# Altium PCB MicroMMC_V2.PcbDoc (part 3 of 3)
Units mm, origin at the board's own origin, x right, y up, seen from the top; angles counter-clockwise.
Board outline 100.01 x 100 mm, 4 copper layers (TOP01, GND02, POWER03, BOTTOM04); 302 components, 195 nets, 1017 pads, 817 vias.
Unrouted connection lines stored in the file: 7.
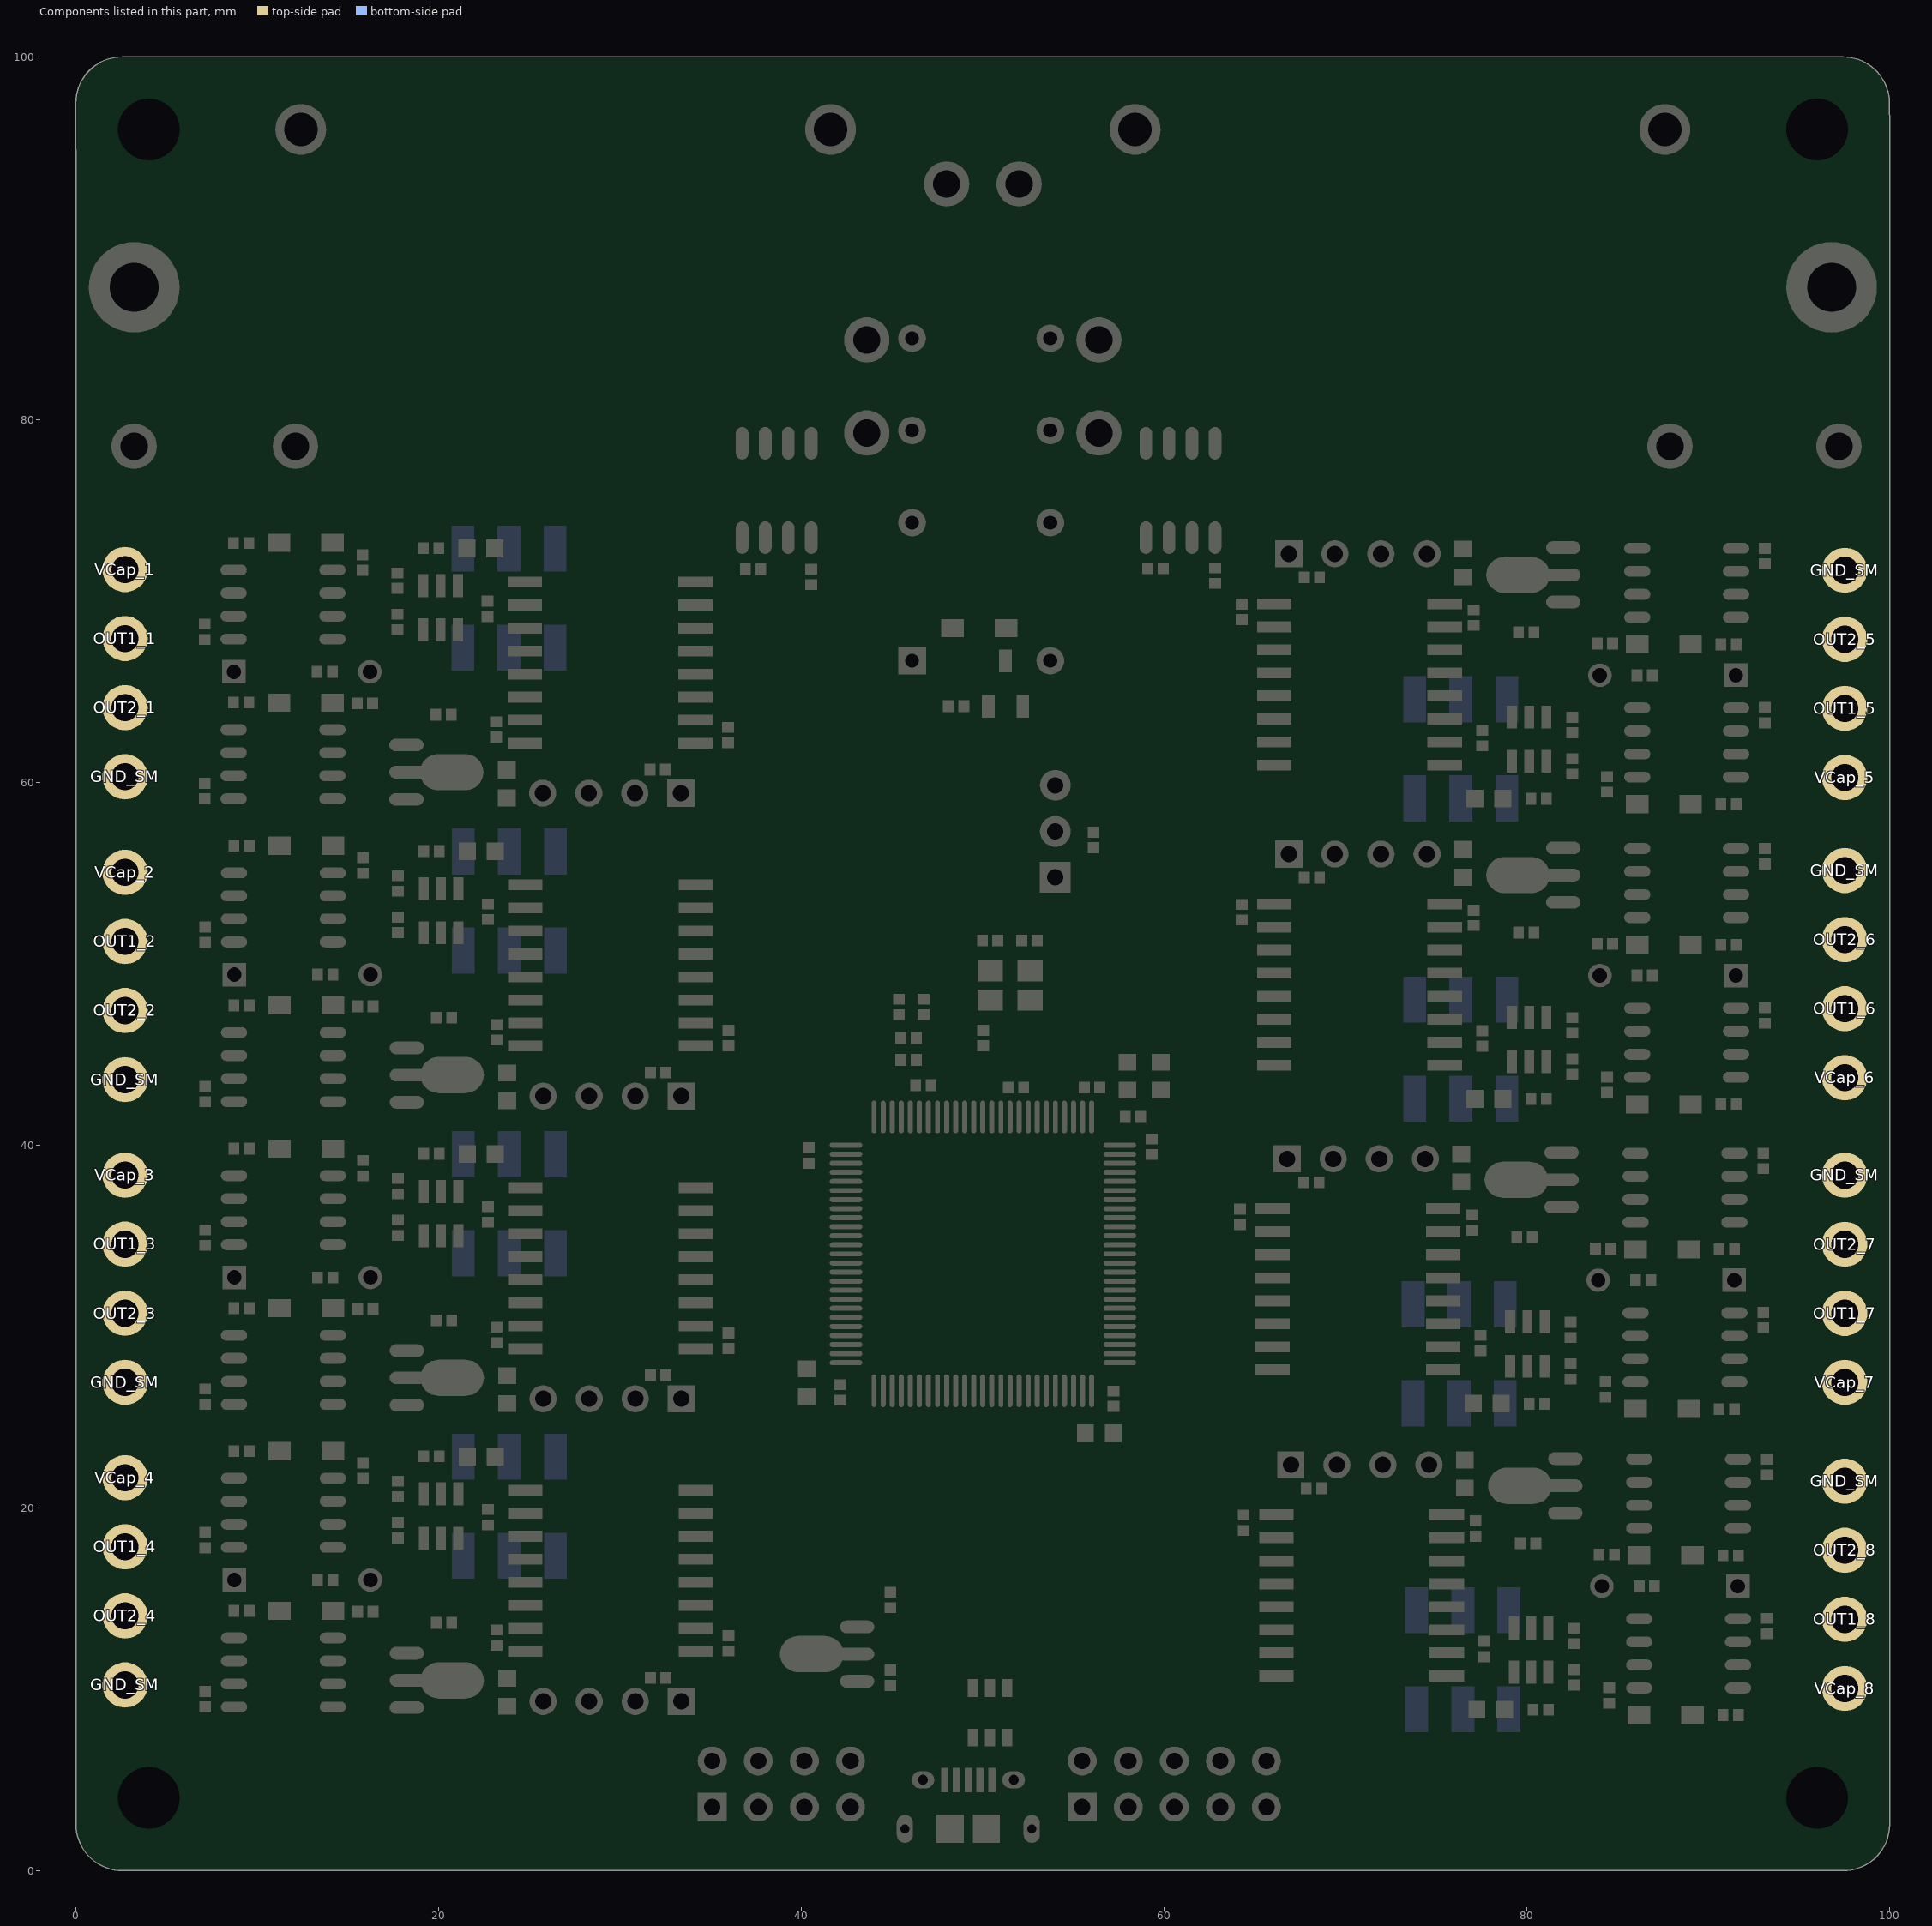
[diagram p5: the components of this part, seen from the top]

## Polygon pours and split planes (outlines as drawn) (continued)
+5 on TOP01 "NONET_L04_P-001" (solid, pour order 937): 63.702,19.245 70.502,19.245 70.502,21.402 70.502,23.674 68.2,23.674 68.2,20.671 63.702,20.671
+5 on TOP01 "NONET_L04_P-001" (solid, pour order 939): 36.6,61.2 32.1,61.2 32.1,58 29.7,58 29.7,62.48 36.6,62.48
GND on TOP01 "NONET_L04_P-001" (solid, remove dead copper, pour order 949): 32.1,74.7 42.5,74.7 42.5,72.5 57.5,72.5 57.5,74.6 57.4,74.7 68.1,74.7 68.1,0.5 68,0.6 32.1,0.6
+5 on TOP01 "TOP01-+5 1" (solid, pour order 928): 39.085,10.785 46.6,10.785 46.6,12.919 37.2,12.919 37.2,12.4 35.648,12.4 32.2,12.4 30.7,12.4 29.7,12.4 29.7,10.1 29.7,7.926 32.1,7.926 32.1,11.369 33.9,11.369 33.9,10.785
GND on TOP01 "TOP01-GND" (solid, pour order 919): 39.1,5 41.4,5 41.4,8.2 46.6,8.2 46.6,10.5 43.949,10.5 43.664,10.785 42.319,10.785 42.114,10.58 42.114,10.435 39.1,10.435 39.1,8.2
VCap_5 on TOP01 "TOP01-VCap_5" (solid, pour order 915): 90.411,64.7 90.411,63.805 94.323,63.805 94.323,66.807 90.698,66.807 86.627,66.807 86.627,64.7
VCap_6 on TOP01 "TOP01-VCap_6" (solid, pour order 914): 90.411,48.144 90.411,47.249 94.323,47.249 94.323,50.251 90.698,50.251 86.627,50.251 86.627,48.144
VCap_7 on TOP01 "TOP01-VCap_7" (solid, pour order 913): 90.32,31.344 90.32,30.449 94.232,30.449 94.232,33.451 90.607,33.451 86.536,33.451 86.536,31.344
VCap_8 on TOP01 "TOP01-VCap_8" (solid, pour order 912): 90.521,14.47 90.521,13.575 94.433,13.575 94.433,16.577 90.808,16.577 86.738,16.577 86.738,14.47
VCap_4 on TOP01 "TOP01-VCap_4" (solid, pour order 911): 9.549,15.12 13.619,15.12 13.619,17.227 9.836,17.227 9.836,18.122 5.924,18.122 5.924,15.12
VCap_3 on TOP01 "TOP01-VCap_3" (solid, pour order 910): 9.549,31.805 13.619,31.805 13.619,33.912 9.836,33.912 9.836,34.807 5.924,34.807 5.924,31.805
VCap_2 on TOP01 "TOP01-VCap_2" (solid, pour order 909): 9.549,48.5 13.619,48.5 13.619,50.607 9.836,50.607 9.836,51.502 5.924,51.502 5.924,48.5
VCap_1 on TOP01 "TOP01-VCap_1" (solid, pour order 908): 9.525,65.2 13.595,65.2 13.595,67.307 9.812,67.307 9.812,68.202 5.9,68.202 5.9,65.2
GND on TOP01 "NONET_L04_P-001" (solid, pour order 903): 57.1,44.1 60.8,44.1 60.8,45.933 57.1,45.933
GND on TOP01 "NONET_L04_P-001" (solid, pour order 902): 47.5,47.494 47.5,44.535 46.59,43.625 46.64,43.575 46.64,40.79 46.36,40.79 46.36,42.39 45.99,42.76 45.99,47.494
3.3V_MC on TOP01 "NONET_L04_P-001" (solid, pour order 901): 44.64,47.744 44.64,49.1 47.44,49.1 47.44,47.744
GND on TOP01 "NONET_L04_P-001" (solid, pour order 899): 55.64,25.891 58.048,25.891 58.048,23.31 56.14,23.31 56.14,24.59 55.36,24.59 55.36,26.083 55.62,26.083 55.64,26.103
+5V_SM on TOP01 "NONET_L04_P-001" (solid, pour order 892): 74.333,11.484 76.687,11.484 76.687,12.634 72.998,12.634 72.998,7.617 74.333,7.617
GND_SM on TOP01 "NONET_L04_P-001" (solid, pour order 884): 77.968,7.777 77.968,10.157 76.67,10.157 76.67,11.027 74.633,11.027 74.633,7.777
GND_SM on TOP01 "NONET_L04_P-001" (solid, pour order 876): 85.303,9.527 85.303,7.777 82.033,7.777 82.033,10.525 83.206,10.525 83.206,9.525
+12_SM on TOP01 "NONET_L04_P-001" (solid, pour order 868): 88.238,7.792 88.238,10.777 83.579,10.777 83.579,9.777 85.471,9.777 85.471,7.788
GND_SM on TOP01 "NONET_L04_P-001" (solid, pour order 860): 94.433,12.178 89.3,12.178 89.3,13.4 94.433,13.4
GND_SM on TOP01 "NONET_L04_P-001" (solid, pour order 852): 99.4,19.778 99.4,23.777 95.533,23.777 95.533,22.127 89.3,22.127 89.3,20.95 95.46,20.95 96.599,19.811
VCap_8 on TOP01 "NONET_L04_P-001" (solid, pour order 844): 95.233,22.252 95.233,23.801 89.3,23.801 89.3,22.252
OUT1_8 on TOP01 "NONET_L04_P-001" (solid, pour order 836): 99.4,11.577 99.4,15.677 94.64,15.677 94.64,11.97 90.521,11.97 90.521,9.147 91.233,9.147 91.233,7.777 95.9,7.777 95.9,11.577
OUT2_8 on TOP01 "NONET_L04_P-001" (solid, pour order 828): 99.4,15.877 94.633,15.877 94.633,16.877 91.358,16.877 91.358,18.177 90.521,18.177 90.521,20.777 95.166,20.777 96.366,19.577 99.4,19.577
+12_SM on TOP01 "NONET_L04_P-001" (solid, pour order 812): 88.175,16.6 84.408,16.6 84.408,18.235 85.538,19.365 88.148,19.365
+5V_SM on TOP01 "NONET_L04_P-001" (solid, pour order 796): 83.683,20.139 83.683,19.695 81.237,17.25 80.191,17.25 80.191,18.79 80.003,18.978 74.098,18.973 74.098,20.219
GND_SM on TOP01 "NONET_L04_P-001" (solid, pour order 788): 83.983,22.171 83.983,20.215 74.098,20.215 74.098,18.73 80.066,18.73 80.066,17.25 71.348,17.25 71.348,23.777 73.267,23.777 73.267,21.342 77.498,21.342 78.566,22.171
+12_SM on TOP01 "NONET_L04_P-001" (solid, pour order 780): 73.267,23.751 73.267,21.447 78.5,21.447 79.225,22.173 79.268,22.13 83.924,22.13 83.924,23.789
+5V_SM on TOP01 "NONET_L04_P-001" (solid, pour order 891): 74.132,28.358 76.485,28.358 76.485,29.508 72.797,29.508 72.797,24.49 74.132,24.491
GND_SM on TOP01 "NONET_L04_P-001" (solid, pour order 883): 77.767,24.651 77.767,27.03 76.468,27.03 76.468,27.901 74.432,27.901 74.432,24.651
GND_SM on TOP01 "NONET_L04_P-001" (solid, pour order 875): 85.102,26.401 85.102,24.651 81.832,24.651 81.832,27.399 83.005,27.399 83.005,26.399
+12_SM on TOP01 "NONET_L04_P-001" (solid, pour order 867): 88.037,24.666 88.037,27.651 83.378,27.651 83.378,26.651 85.27,26.651 85.27,24.662
GND_SM on TOP01 "NONET_L04_P-001" (solid, pour order 859): 94.232,29.052 89.3,29.052 89.3,30.3 94.232,30.3
GND_SM on TOP01 "NONET_L04_P-001" (solid, pour order 851): 99.332,36.651 99.332,40.651 95.332,40.651 95.332,39.001 89.3,39.001 89.3,37.824 95.259,37.824 96.398,36.685
VCap_7 on TOP01 "NONET_L04_P-001" (solid, pour order 843): 95.032,39.126 95.032,40.675 89.3,40.675 89.3,39.126
OUT1_7 on TOP01 "NONET_L04_P-001" (solid, pour order 835): 99.332,28.451 99.332,32.551 94.438,32.551 94.438,28.844 90.32,28.844 90.32,26.021 91.032,26.021 91.032,24.651 95.832,24.651 95.832,28.451
OUT2_7 on TOP01 "NONET_L04_P-001" (solid, pour order 827): 99.332,32.751 94.432,32.751 94.432,33.751 91.157,33.751 91.157,35.051 90.32,35.051 90.32,37.651 94.965,37.651 96.165,36.451 99.332,36.451
+12_SM on TOP01 "NONET_L04_P-001" (solid, pour order 811): 87.974,33.474 84.207,33.474 84.207,35.109 85.337,36.239 87.947,36.239
+5V_SM on TOP01 "NONET_L04_P-001" (solid, pour order 795): 83.482,37.013 83.482,36.569 81.036,34.124 79.99,34.124 79.99,35.664 79.802,35.852 73.896,35.847 73.897,37.093
GND_SM on TOP01 "NONET_L04_P-001" (solid, pour order 787): 83.782,39.045 83.782,37.089 73.897,37.089 73.897,35.604 79.864,35.604 79.864,34.124 71.147,34.124 71.147,40.651 73.066,40.651 73.066,38.216 77.297,38.216 78.364,39.045
+12_SM on TOP01 "NONET_L04_P-001" (solid, pour order 779): 73.066,40.625 73.066,38.321 78.298,38.321 79.023,39.047 79.066,39.004 83.723,39.004 83.723,40.663
+5V_SM on TOP01 "NONET_L04_P-001" (solid, pour order 890): 74.223,45.158 76.576,45.158 76.576,46.308 72.888,46.308 72.888,41.291 74.223,41.291
GND_SM on TOP01 "NONET_L04_P-001" (solid, pour order 882): 77.858,41.451 77.858,43.831 76.559,43.831 76.559,44.701 74.523,44.701 74.523,41.451
GND_SM on TOP01 "NONET_L04_P-001" (solid, pour order 874): 85.193,43.201 85.193,41.451 81.923,41.451 81.923,44.199 83.096,44.199 83.096,43.199
+12_SM on TOP01 "NONET_L04_P-001" (solid, pour order 866): 88.128,41.466 88.128,44.451 83.469,44.451 83.469,43.451 85.361,43.451 85.361,41.462
GND_SM on TOP01 "NONET_L04_P-001" (solid, pour order 858): 94.323,45.852 89.3,45.852 89.3,47.026 94.323,47.026
GND_SM on TOP01 "NONET_L04_P-001" (solid, pour order 850): 99.423,53.451 99.423,57.451 95.423,57.451 95.423,55.801 89.3,55.801 89.3,54.624 95.35,54.624 96.489,53.485
VCap_6 on TOP01 "NONET_L04_P-001" (solid, pour order 842): 95.123,55.926 95.123,57.475 89.3,57.475 89.3,55.926
OUT1_6 on TOP01 "NONET_L04_P-001" (solid, pour order 834): 99.423,45.251 99.423,49.351 94.529,49.351 94.529,45.644 90.411,45.644 90.411,42.821 91.123,42.821 91.123,41.451 95.923,41.451 95.923,45.251
OUT2_6 on TOP01 "NONET_L04_P-001" (solid, pour order 826): 99.423,49.551 94.523,49.551 94.523,50.551 91.248,50.551 91.248,51.851 90.411,51.851 90.411,54.451 95.056,54.451 96.256,53.251 99.423,53.251
+12_SM on TOP01 "NONET_L04_P-001" (solid, pour order 810): 88.065,50.274 84.298,50.274 84.298,51.909 85.428,53.039 88.038,53.039
+5V_SM on TOP01 "NONET_L04_P-001" (solid, pour order 794): 83.573,53.813 83.573,53.369 81.127,50.924 80.08,50.924 80.08,52.464 79.893,52.652 73.987,52.647 73.987,53.893
GND_SM on TOP01 "NONET_L04_P-001" (solid, pour order 786): 83.873,55.845 83.873,53.889 73.987,53.889 73.987,52.404 79.955,52.404 79.955,50.924 71.238,50.924 71.238,57.451 73.157,57.451 73.157,55.016 77.388,55.016 78.455,55.845
+12_SM on TOP01 "NONET_L04_P-001" (solid, pour order 778): 73.157,57.425 73.157,55.121 78.389,55.121 79.114,55.847 79.157,55.804 83.814,55.804 83.814,57.463
+12_SM on TOP01 "NONET_L04_P-001" (solid, pour order 777): 73.157,73.981 73.157,71.677 78.389,71.677 79.114,72.403 79.157,72.36 83.814,72.36 83.814,74.019
GND_SM on TOP01 "NONET_L04_P-001" (solid, remove dead copper, pour order 785): 83.873,72.401 83.873,70.445 73.987,70.445 73.987,68.96 79.955,68.96 79.955,67.48 71.238,67.48 71.238,74.007 73.157,74.007 73.157,71.572 77.388,71.572 78.455,72.401
+5V_SM on TOP01 "NONET_L04_P-001" (solid, pour order 793): 83.573,70.369 83.573,69.925 81.127,67.48 80.08,67.48 80.08,69.02 79.893,69.208 73.987,69.203 73.987,70.449
+12_SM on TOP01 "NONET_L04_P-001" (solid, pour order 809): 88.065,66.83 84.298,66.83 84.298,68.465 85.428,69.595 88.038,69.595
OUT2_5 on TOP01 "NONET_L04_P-001" (solid, pour order 825): 99.423,66.107 94.523,66.107 94.523,67.107 91.248,67.107 91.248,68.407 90.411,68.407 90.411,71.007 95.056,71.007 96.256,69.807 99.423,69.807
OUT1_5 on TOP01 "NONET_L04_P-001" (solid, pour order 833): 99.423,61.807 99.423,65.907 94.529,65.907 94.529,62.2 90.411,62.2 90.411,59.377 91.123,59.377 91.123,58.007 95.923,58.007 95.923,61.807
VCap_5 on TOP01 "NONET_L04_P-001" (solid, pour order 841): 95.123,72.482 95.123,74.031 89.3,74.031 89.3,72.482
GND_SM on TOP01 "NONET_L04_P-001" (solid, pour order 849): 99.423,70.007 99.423,74.007 95.423,74.007 95.423,72.357 89.3,72.357 89.3,71.18 95.35,71.18 96.489,70.041
GND_SM on TOP01 "NONET_L04_P-001" (solid, pour order 857): 94.323,62.408 89.3,62.408 89.3,63.6 94.323,63.6
+12_SM on TOP01 "NONET_L04_P-001" (solid, pour order 865): 88.128,58.022 88.128,61.007 83.469,61.007 83.469,60.007 85.361,60.007 85.361,58.018
GND_SM on TOP01 "NONET_L04_P-001" (solid, pour order 873): 85.193,59.757 85.193,58.007 81.923,58.007 81.923,60.755 83.096,60.755 83.096,59.755
GND_SM on TOP01 "NONET_L04_P-001" (solid, pour order 881): 77.858,58.007 77.858,60.387 76.559,60.387 76.559,61.257 74.523,61.257 74.523,58.007
+5V_SM on TOP01 "NONET_L04_P-001" (solid, pour order 889): 74.223,61.714 76.576,61.714 76.576,62.864 72.888,62.864 72.888,57.847 74.223,57.847
+12_SM on TOP01 "NONET_L04_P-001" (solid, pour order 776): 27.09,7.946 27.09,10.249 21.857,10.249 21.132,9.524 21.089,9.567 16.432,9.567 16.432,7.908
+5V_SM on TOP01 "NONET_L04_P-001" (solid, pour order 792): 16.674,11.558 16.674,12.001 19.119,14.447 20.166,14.447 20.166,12.907 20.354,12.719 26.259,12.723 26.259,11.478
GND_SM on TOP01 "NONET_L04_P-001" (solid, pour order 784): 16.374,9.525 16.374,11.482 26.259,11.482 26.259,12.967 20.291,12.967 20.291,14.447 29,14.447 29,7.92 27.09,7.92 27.09,10.355 22.859,10.355 21.791,9.525
+12_SM on TOP01 "NONET_L04_P-001" (solid, pour order 808): 12.181,15.097 15.949,15.097 15.949,13.462 14.818,12.332 12.209,12.332
OUT2_4 on TOP01 "NONET_L04_P-001" (solid, pour order 824): 0.824,15.82 5.724,15.82 5.724,14.82 8.999,14.82 8.999,13.52 9.836,13.52 9.836,10.92 5.191,10.92 3.991,12.12 0.824,12.12
VCap_4 on TOP01 "NONET_L04_P-001" (solid, pour order 840): 5.124,9.445 5.124,7.896 10.9,7.896 10.9,9.445
GND_SM on TOP01 "NONET_L04_P-001" (solid, pour order 848): 0.824,11.92 0.824,7.92 4.824,7.92 4.824,9.57 10.9,9.57 10.9,10.747 4.897,10.747 3.758,11.886
OUT1_4 on TOP01 "NONET_L04_P-001" (solid, pour order 832): 0.824,20.12 0.824,16.02 5.717,16.02 5.717,19.727 9.836,19.727 9.836,22.55 9.124,22.55 9.124,23.92 4.324,23.92 4.324,20.12
GND_SM on TOP01 "NONET_L04_P-001" (solid, pour order 856): 5.924,19.519 10.9,19.519 10.9,18.3 5.924,18.3
+12_SM on TOP01 "NONET_L04_P-001" (solid, pour order 864): 12.119,23.905 12.119,20.92 16.778,20.92 16.778,21.92 14.886,21.92 14.886,23.908
GND_SM on TOP01 "NONET_L04_P-001" (solid, pour order 872): 15.054,22.169 15.054,23.92 18.324,23.92 18.324,21.172 17.151,21.172 17.151,22.172
GND_SM on TOP01 "NONET_L04_P-001" (solid, pour order 880): 22.388,23.92 22.388,21.54 23.687,21.54 23.687,20.67 25.723,20.67 25.723,23.92
+5V_SM on TOP01 "NONET_L04_P-001" (solid, pour order 888): 26.024,20.213 23.67,20.213 23.67,19.063 27.358,19.063 27.358,24.08 26.024,24.08
+12_SM on TOP01 "NONET_L04_P-001" (solid, pour order 775): 27.09,24.631 27.09,26.934 21.857,26.934 21.132,26.209 21.089,26.252 16.432,26.252 16.432,24.593
+5V_SM on TOP01 "NONET_L04_P-001" (solid, pour order 791): 16.674,28.243 16.674,28.686 19.119,31.132 20.166,31.132 20.166,29.592 20.354,29.404 26.259,29.408 26.259,28.163
GND_SM on TOP01 "NONET_L04_P-001" (solid, pour order 783): 16.374,26.21 16.374,28.167 26.259,28.167 26.259,29.652 20.291,29.652 20.291,31.132 29,31.132 29,24.605 27.09,24.605 27.09,27.04 22.859,27.04 21.791,26.21
+12_SM on TOP01 "NONET_L04_P-001" (solid, pour order 807): 12.181,31.782 15.949,31.782 15.949,30.147 14.818,29.017 12.209,29.017
OUT2_3 on TOP01 "NONET_L04_P-001" (solid, pour order 823): 0.824,32.505 5.724,32.505 5.724,31.505 8.999,31.505 8.999,30.205 9.836,30.205 9.836,27.605 5.191,27.605 3.991,28.805 0.824,28.805
VCap_3 on TOP01 "NONET_L04_P-001" (solid, pour order 839): 5.124,26.13 5.124,24.581 10.9,24.581 10.9,26.13
GND_SM on TOP01 "NONET_L04_P-001" (solid, pour order 847): 0.824,28.605 0.824,24.605 4.824,24.605 4.824,26.255 10.9,26.255 10.9,27.432 4.897,27.432 3.758,28.571
OUT1_3 on TOP01 "NONET_L04_P-001" (solid, pour order 831): 0.824,36.805 0.824,32.705 5.717,32.705 5.717,36.412 9.836,36.412 9.836,39.235 9.124,39.235 9.124,40.605 4.324,40.605 4.324,36.805
GND_SM on TOP01 "NONET_L04_P-001" (solid, pour order 855): 5.924,36.204 10.9,36.204 10.9,34.905 5.924,34.905
+12_SM on TOP01 "NONET_L04_P-001" (solid, pour order 863): 12.119,40.59 12.119,37.605 16.778,37.605 16.778,38.605 14.886,38.605 14.886,40.593
GND_SM on TOP01 "NONET_L04_P-001" (solid, pour order 871): 15.054,38.854 15.054,40.605 18.324,40.605 18.324,37.856 17.151,37.856 17.151,38.857
GND_SM on TOP01 "NONET_L04_P-001" (solid, pour order 879): 22.388,40.605 22.388,38.225 23.687,38.225 23.687,37.355 25.723,37.355 25.723,40.605
+5V_SM on TOP01 "NONET_L04_P-001" (solid, pour order 887): 26.024,36.898 23.67,36.898 23.67,35.748 27.358,35.748 27.358,40.765 26.024,40.765
+12_SM on TOP01 "NONET_L04_P-001" (solid, pour order 774): 27.09,41.326 27.09,43.629 21.857,43.629 21.132,42.904 21.089,42.947 16.432,42.947 16.432,41.288
+5V_SM on TOP01 "NONET_L04_P-001" (solid, pour order 790): 16.674,44.938 16.674,45.381 19.119,47.827 20.166,47.827 20.166,46.287 20.354,46.099 26.259,46.103 26.259,44.858
GND_SM on TOP01 "NONET_L04_P-001" (solid, pour order 782): 16.374,42.905 16.374,44.862 26.259,44.862 26.259,46.347 20.291,46.347 20.291,47.827 29,47.827 29,41.3 27.09,41.3 27.09,43.735 22.859,43.735 21.791,42.905
+12_SM on TOP01 "NONET_L04_P-001" (solid, pour order 806): 12.181,48.477 15.949,48.477 15.949,46.842 14.818,45.712 12.209,45.712
OUT2_2 on TOP01 "NONET_L04_P-001" (solid, pour order 822): 0.824,49.2 5.724,49.2 5.724,48.2 8.999,48.2 8.999,46.9 9.836,46.9 9.836,44.3 5.191,44.3 3.991,45.5 0.824,45.5
VCap_2 on TOP01 "NONET_L04_P-001" (solid, pour order 838): 5.124,42.825 5.124,41.276 10.9,41.276 10.9,42.825
GND_SM on TOP01 "NONET_L04_P-001" (solid, pour order 846): 0.824,45.3 0.824,41.3 4.824,41.3 4.824,42.95 10.9,42.95 10.9,44.127 4.897,44.127 3.758,45.266
OUT1_2 on TOP01 "NONET_L04_P-001" (solid, pour order 830): 0.824,53.5 0.824,49.4 5.717,49.4 5.717,53.107 9.836,53.107 9.836,55.93 9.124,55.93 9.124,57.3 4.324,57.3 4.324,53.5
GND_SM on TOP01 "NONET_L04_P-001" (solid, pour order 854): 5.924,52.899 10.9,52.899 10.9,51.7 5.924,51.7
+12_SM on TOP01 "NONET_L04_P-001" (solid, pour order 862): 12.119,57.285 12.119,54.3 16.778,54.3 16.778,55.3 14.886,55.3 14.886,57.288
GND_SM on TOP01 "NONET_L04_P-001" (solid, pour order 870): 15.054,55.549 15.054,57.3 18.324,57.3 18.324,54.552 17.151,54.552 17.151,55.552
GND_SM on TOP01 "NONET_L04_P-001" (solid, pour order 878): 22.388,57.3 22.388,54.92 23.687,54.92 23.687,54.05 25.723,54.05 25.723,57.3
+5V_SM on TOP01 "NONET_L04_P-001" (solid, pour order 886): 26.024,53.593 23.67,53.593 23.67,52.443 27.358,52.443 27.358,57.46 26.024,57.46
+5V_SM on TOP01 "NONET_L04_P-001" (solid, pour order 885): 26,70.293 23.646,70.293 23.646,69.143 27.335,69.143 27.335,74.16 26,74.16
GND_SM on TOP01 "NONET_L04_P-001" (solid, pour order 877): 22.365,74 22.365,71.62 23.663,71.62 23.663,70.75 25.7,70.75 25.7,74
GND_SM on TOP01 "NONET_L04_P-001" (solid, pour order 869): 15.03,72.249 15.03,74 18.3,74 18.3,71.252 17.127,71.252 17.127,72.252
+12_SM on TOP01 "NONET_L04_P-001" (solid, pour order 861): 12.095,73.985 12.095,71 16.754,71 16.754,72 14.862,72 14.862,73.988
GND_SM on TOP01 "NONET_L04_P-001" (solid, pour order 853): 5.9,69.599 10.9,69.599 10.9,68.4 5.9,68.4
OUT1_1 on TOP01 "NONET_L04_P-001" (solid, pour order 829): 4.3,71.092 3.408,70.2 1.7,70.2 0.8,70.2 0.8,66.1 5.693,66.1 5.693,69.807 9.812,69.807 9.812,72.63 9.1,72.63 9.1,74 4.3,74
GND_SM on TOP01 "NONET_L04_P-001" (solid, pour order 845): 0.8,62 0.8,58 4.8,58 4.8,59.65 10.9,59.65 10.9,60.827 4.873,60.827 3.734,61.966
VCap_1 on TOP01 "NONET_L04_P-001" (solid, pour order 837): 5.1,59.525 5.1,57.976 10.9,57.976 10.9,59.525
OUT2_1 on TOP01 "NONET_L04_P-001" (solid, pour order 821): 0.8,65.9 5.7,65.9 5.7,64.9 8.975,64.9 8.975,63.6 9.812,63.6 9.812,61 5.167,61 3.967,62.2 0.8,62.2
+12_SM on TOP01 "NONET_L04_P-001" (solid, pour order 805): 12.158,65.177 15.925,65.177 15.925,63.542 14.795,62.412 12.185,62.412
GND_SM on TOP01 "NONET_L04_P-001" (solid, pour order 781): 16.35,59.605 16.35,61.562 26.235,61.562 26.235,63.047 20.267,63.047 20.267,64.527 28.956,64.527 28.956,58 27.066,58 27.066,60.435 22.835,60.435 21.767,59.605
+5V_SM on TOP01 "NONET_L04_P-001" (solid, pour order 789): 16.65,61.638 16.65,62.081 19.096,64.527 20.142,64.527 20.142,62.987 20.33,62.799 26.235,62.803 26.235,61.558
+12_SM on TOP01 "NONET_L04_P-001" (solid, pour order 773): 27.066,58.026 27.066,60.329 21.833,60.329 21.108,59.604 21.065,59.647 16.409,59.647 16.409,57.988
Rcharge2 on TOP01 "RCHARGE2_L01_P724" (solid, pour order 724): 41.5,80.3 41.5,78.4 42.3,77.6 45.993,77.6 47.1,78.707 47.1,80.15 46.15,81.1 42.3,81.1
Out1 on TOP01 "OUT1_L01_P739" (solid, pour order 739): 51.4,73.1 54.4,73.1 55.2,73.9 55.2,75.8 52.5,78.5 52.5,88.5 54.3,90.3 54.3,96 53.9,96.4 50.5,96.4 50.1,96 50.1,74.4
IP-I1 on TOP01 "IP-I1_L01_P740" (solid, pour order 740): 52.7,83.8 54,82.5 57.6,82.5 58.4,81.7 58.4,77.5 60.7,77.5 60.7,84.746 58.944,86.5 53.8,86.5 52.7,85.4
IP+I1 on TOP01 "IP+I1_L01_P723" (solid, pour order 723): 63.424,77.5 60.898,77.5 60.898,87.002 55.1,92.8 55.1,99.3 63.463,99.3
3.3V_MC on TOP01 "3.3V_L04_P-001" (solid, pour order 715): 53.6,13.081 39.814,13.081 39.814,14.925 53.6,14.925
IP-I2 on TOP01 "IP-I2_L01_P721" (solid, pour order 721): 38.635,77.5 38.635,86.609 45,93.001 45,99.3 36.1,99.3 36.1,77.5
Out2 on TOP01 "OUT2_L01_P726" (solid, pour order 726): 44.7,73.9 45.5,73.1 48.6,73.1 49.9,74.4 49.9,96 49.5,96.4 46.2,96.4 45.8,96 45.8,90 47.3,88.5 47.3,78.6 44.7,76
StackBottom2 on TOP01 "STACKBOTTOM2_L01_P718" (solid, pour order 718): 0.7,90.3 6.1,90.3 6.1,76.843 0.7,76.843
Rcharge1 on TOP01 "RCHARGE1_L01_P725" (solid, pour order 725): 58.2,78.4 58.2,80.226 57.426,81 53.6,81 52.7,80.1 52.7,78.6 53.7,77.6 57.4,77.6
IP+I2 on TOP01 "IP+I2_L01_P722" (solid, pour order 722): 38.635,77.5 41.2,77.5 41.2,81.7 42,82.5 45.849,82.5 47.1,83.751 47.1,85.232 45.832,86.5 41,86.5 38.635,84.135
StackBottom1 on TOP01 "STACKBOTTOM1_L01_P720" (solid, pour order 720): 84.3,76.9 91.1,76.9 91.1,99.3 84.3,99.3
StackTop1 on TOP01 "STACKTOP1_L01_P719" (solid, pour order 719): 94.2,90.417 99.4,90.417 99.4,77 94.2,77
StackTop2 on TOP01 "STACKTOP2_L01_P717" (solid, pour order 717): 8.8,76.937 16.1,76.937 16.1,99.4 8.8,99.4
GND on GND02 "GND02-GND" (solid, pour order 905): 68.2,74.7 57.465,74.7 57.465,72.5 42.5,72.5 42.5,74.7 32.1,74.7 32.1,7.7 32.1,0.5 68.2,0.5
GND_SM on GND02 "NONET_L04_P-001" (solid, pour order 748): 99.4,23.784 99.4,7.784 71.348,7.784 71.348,23.784
GND_SM on GND02 "NONET_L04_P-001" (solid, pour order 747): 99.332,40.658 99.332,24.658 71.147,24.658 71.147,40.658
GND_SM on GND02 "NONET_L04_P-001" (solid, pour order 746): 99.423,57.458 99.423,41.458 71.238,41.458 71.238,57.458
GND_SM on GND02 "NONET_L04_P-001" (solid, pour order 745): 99.423,74.014 99.423,58.014 71.238,58.014 71.238,74.014
GND_SM on GND02 "NONET_L04_P-001" (solid, pour order 744): 0.824,7.913 0.824,23.913 29,23.913 29,7.913
GND_SM on GND02 "NONET_L04_P-001" (solid, pour order 743): 0.824,24.598 0.824,40.598 29,40.598 29,24.598
GND_SM on GND02 "NONET_L04_P-001" (solid, pour order 742): 0.824,41.293 0.824,57.293 29,57.293 29,41.293
GND_SM on GND02 "NONET_L04_P-001" (solid, pour order 741): 0.8,57.993 0.8,73.993 29,73.993 29,57.993
+5 on POWER03 "POWER03-+5" (solid, pour order 929): 20 vertices, not listed, extent 29.7,1.419 68.2,74.7
+5 on POWER03 "NONET_L04_P-001" (solid, pour order 938): 29.8,29.1 29.8,24.6 32.4,24.6 32.4,29.1
+5 on POWER03 "NONET_L04_P-001" (solid, pour order 940): 29.755,45.819 29.755,41.319 32.355,41.319 32.355,45.819
+5 on POWER03 "NONET_L04_P-001" (solid, pour order 941): 29.731,62.519 29.731,58.019 32.331,58.019 32.331,62.519
+5 on POWER03 "NONET_L04_P-001" (solid, pour order 942): 67.745,74 67.745,69.5 70.3,69.5 70.3,74
+5 on POWER03 "NONET_L04_P-001" (solid, pour order 943): 67.845,57.4 67.845,53 70.4,53 70.4,57.4
+5 on POWER03 "NONET_L04_P-001" (solid, pour order 944): 67.816,40.6 67.816,36.183 70.4,36.183 70.4,40.6
+5 on POWER03 "NONET_L04_P-001" (solid, pour order 945): 67.916,23.7 67.916,19.283 70.516,19.283 70.516,23.7
+12_SM on POWER03 "NONET_L04_P-001" (solid, pour order 804): 73.5,37.343 73.5,40.651 86.72,40.651 86.72,24.651 83.632,24.651 83.782,24.801 83.782,37.316
+5V_SM on POWER03 "NONET_L04_P-001" (solid, pour order 797): 83.673,7.777 83.673,20.215 71.9,20.215 71.9,7.777
+12_SM on POWER03 "NONET_L04_P-001" (solid, pour order 893): 73.4,20.47 73.4,23.777 86.921,23.777 86.921,7.777 83.833,7.777 83.983,7.927 83.983,20.442
VCap_8 on POWER03 "NONET_L04_P-001" (solid, pour order 757): 99.4,7.744 87.038,7.744 87.038,23.777 99.4,23.777
+5V_SM on POWER03 "NONET_L04_P-001" (solid, pour order 764): 83.472,24.651 83.472,37.089 71.7,37.089 71.7,24.651
VCap_7 on POWER03 "NONET_L04_P-001" (solid, pour order 756): 99.332,24.651 99.299,24.618 86.836,24.618 86.836,40.651 99.332,40.651
+12_SM on POWER03 "NONET_L04_P-001" (solid, pour order 803): 73.4,54.144 73.4,57.451 86.811,57.451 86.811,41.451 83.723,41.451 83.873,41.601 83.873,54.116
+5V_SM on POWER03 "NONET_L04_P-001" (solid, pour order 763): 83.563,41.451 83.563,53.889 71.8,53.889 71.8,41.451
VCap_6 on POWER03 "NONET_L04_P-001" (solid, pour order 755): 99.423,41.451 99.39,41.418 86.927,41.418 86.927,57.451 99.423,57.451
VCap_5 on POWER03 "NONET_L04_P-001" (solid, pour order 754): 99.423,58.007 99.39,57.974 86.927,57.974 86.927,74.007 99.423,74.007
+5V_SM on POWER03 "NONET_L04_P-001" (solid, pour order 762): 83.563,58.007 83.563,70.445 71.8,70.445 71.8,58.007
+12_SM on POWER03 "NONET_L04_P-001" (solid, pour order 802): 73.4,70.7 73.4,74.007 86.811,74.007 86.811,58.007 83.723,58.007 83.873,58.157 83.873,70.672
+5V_SM on POWER03 "NONET_L04_P-001" (solid, pour order 761): 16.683,23.92 16.683,11.482 28.4,11.482 28.4,23.92
VCap_4 on POWER03 "NONET_L04_P-001" (solid, pour order 753): 0.824,23.92 0.856,23.952 13.319,23.952 13.319,7.92 0.824,7.92
+12_SM on POWER03 "NONET_L04_P-001" (solid, pour order 801): 27.1,11.226 27.1,7.92 13.436,7.92 13.436,23.92 16.524,23.92 16.374,23.77 16.374,11.255
+5V_SM on POWER03 "NONET_L04_P-001" (solid, pour order 760): 16.683,40.605 16.683,28.167 28.4,28.167 28.4,40.605
VCap_3 on POWER03 "NONET_L04_P-001" (solid, pour order 752): 0.824,40.605 0.856,40.637 13.319,40.637 13.319,24.605 0.824,24.605
+12_SM on POWER03 "NONET_L04_P-001" (solid, pour order 800): 27.1,27.911 27.1,24.605 13.436,24.605 13.436,40.605 16.524,40.605 16.374,40.455 16.374,27.94
+5V_SM on POWER03 "NONET_L04_P-001" (solid, pour order 759): 16.683,57.3 16.683,44.862 28.4,44.862 28.4,57.3
VCap_2 on POWER03 "NONET_L04_P-001" (solid, pour order 751): 0.824,57.3 0.856,57.332 13.319,57.332 13.319,41.3 0.824,41.3
+12_SM on POWER03 "NONET_L04_P-001" (solid, pour order 799): 27.1,44.606 27.1,41.3 13.436,41.3 13.436,57.3 16.524,57.3 16.374,57.15 16.374,44.635
3.3V_MC on POWER03 "NONET_L04_P-001" (solid, remove dead copper, pour order 749): 38.839,55.8 60.6,55.8 60.6,13.085 53.6,13.085 38.839,13.085
+12_SM on POWER03 "NONET_L04_P-001" (solid, pour order 798): 27.066,61.306 27.066,58 13.412,58 13.412,74 16.5,74 16.35,73.85 16.35,61.335
VCap_1 on POWER03 "NONET_L04_P-001" (solid, pour order 750): 0.8,74 0.832,74.032 13.295,74.032 13.295,58 0.8,58
+5V_SM on POWER03 "NONET_L04_P-001" (solid, pour order 758): 16.66,74 16.66,61.562 28.4,61.562 28.4,74
StackTop1 on BOTTOM04 "STACKTOP1_L04_P738" (solid, pour order 738): 94.2,90.4 99.4,90.4 99.4,77 94.2,77
Rcharge2 on BOTTOM04 "RCHARGE2_L04_P731" (solid, pour order 731): 41.5,80.3 41.5,78.4 42.3,77.6 46,77.6 47.1,78.7 47.1,80.1 46.1,81.1 42.3,81.1
IP-I1 on BOTTOM04 "IP-I1_L04_P735" (solid, pour order 735): 52.7,83.8 54,82.5 57.6,82.5 58.4,81.7 58.4,77.5 60.7,77.5 60.7,84.746 58.944,86.5 53.8,86.5 52.7,85.4
Out2 on BOTTOM04 "OUT2_L04_P733" (solid, pour order 733): 44.7,76 44.7,73.9 45.5,73.1 48.6,73.1 49.9,74.4 49.9,96 49.5,96.4 46.2,96.4 45.8,96 45.8,90 47.3,88.5 47.3,78.6
Out1 on BOTTOM04 "OUT1_L04_P734" (solid, pour order 734): 51.4,73.1 50.1,74.4 50.1,96 50.5,96.4 53.9,96.4 54.3,96 54.3,90.3 52.5,88.5 52.5,78.5 55.2,75.8 55.2,73.9 54.4,73.1
StackBottom1 on BOTTOM04 "STACKBOTTOM1_L04_P737" (solid, pour order 737): 84.3,99.3 91.1,99.3 91.1,76.9 84.3,76.9
IP+I1 on BOTTOM04 "IP+I1_L04_P736" (solid, pour order 736): 55.1,99.3 55.1,92.8 60.9,87 60.9,77.5 63.4,77.5 63.4,99.3
Rcharge1 on BOTTOM04 "RCHARGE1_L04_P732" (solid, pour order 732): 52.7,78.6 53.7,77.6 57.384,77.6 58.2,78.416 58.2,80.236 57.436,81 53.6,81 52.7,80.1
IP+I2 on BOTTOM04 "IP+I2_L04_P730" (solid, pour order 730): 41.2,77.5 41.2,81.7 42,82.5 45.849,82.5 47.1,83.751 47.1,85.249 45.849,86.5 41,86.5 38.635,84.135 38.635,77.5
IP-I2 on BOTTOM04 "IP-I2_L04_P729" (solid, pour order 729): 36.1,77.5 36.1,99.3 45,99.3 45,93.2 38.635,86.801 38.635,77.5
StackTop2 on BOTTOM04 "STACKTOP2_L04_P728" (solid, pour order 728): 8.8,76.943 16.1,76.943 16.1,99.3 8.8,99.3
StackBottom2 on BOTTOM04 "STACKBOTTOM2_L04_P727" (solid, pour order 727): 6.1,76.843 6.1,90.3 0.7,90.3 0.7,76.843

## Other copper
Multi-Layer:
  pour cut-out: 99.417,7.6 99.583,7.6 99.583,23.999 99.4,23.999
  pour cut-out: 99.317,24.5 99.483,24.5 99.483,40.899 99.3,40.899
  pour cut-out: 99.39,41.202 99.555,41.202 99.555,57.601 99.373,57.601
  pour cut-out: 70.87,75.3 70.87,74.048 70.57,74.048 70.57,75.3
  pour cut-out: 99.5,7.77 70.933,7.77 70.933,23.772 99.5,23.772 99.5,23.992 70.683,23.992 70.683,7.545 99.5,7.545
  pour cut-out: 99.432,24.644 70.732,24.644 70.732,40.646 99.482,40.646 99.482,40.866 70.482,40.866 70.482,24.419 99.432,24.419
  pour cut-out: 99.523,41.444 70.823,41.444 70.823,57.446 99.573,57.446 99.573,57.666 70.573,57.666 70.573,41.219 99.523,41.219
  pour cut-out: 99.39,57.802 99.555,57.802 99.555,74.201 99.373,74.201
  pour cut-out: 99.523,58 70.823,58 70.823,74.002 99.573,74.002 99.573,74.222 70.573,74.222 70.573,57.775 99.523,57.775
  pour cut-out: 0.724,40.612 29.423,40.612 29.423,24.61 0.673,24.61 0.673,24.39 29.673,24.39 29.673,40.837 0.724,40.837
  pour cut-out: 0.856,24.125 0.691,24.125 0.691,7.726 0.874,7.726
  pour cut-out: 0.856,40.81 0.691,40.81 0.691,24.411 0.874,24.411
  pour cut-out: 0.856,57.505 0.691,57.505 0.691,41.106 0.874,41.106
  pour cut-out: 42.5,74.7 42.5,72.5 57.465,72.5 57.465,74.7 70.8,74.7 70.8,75.3 57,75.3 57,73 43.1,73 43.1,75.3 29.2,75.3 29.2,74.7
  pour cut-out: 0.833,74.205 0.667,74.205 0.667,57.806 0.85,57.806
  pour cut-out: 0.7,74.007 29.4,74.007 29.4,58.005 0.65,58.005 0.65,57.785 29.65,57.785 29.65,74.232 0.7,74.232
  pour cut-out: 0.856,57.505 0.691,57.505 0.691,41.106 0.874,41.106
  pour cut-out: 0.724,57.307 29.423,57.307 29.423,41.305 0.673,41.305 0.673,41.085 29.673,41.085 29.673,57.532 0.724,57.532
  pour cut-out: 0.856,40.81 0.691,40.81 0.691,24.411 0.874,24.411
  pour cut-out: 0.856,24.125 0.691,24.125 0.691,7.726 0.874,7.726
  pour cut-out: 0.724,23.927 29.423,23.927 29.423,7.925 0.673,7.925 0.673,7.705 29.673,7.705 29.673,24.152 0.724,24.152
  pour cut-out: 29.6,75.3 29.6,74.048 29.2,74.048 29.2,75.3

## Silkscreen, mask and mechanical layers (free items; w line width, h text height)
Top Overlay:
  drawing of 229 lines, arcs and shapes, not listed
  text "Out2" at 46.194,94.703 h1.02
  text "Out1" at 50.403,94.703 h1.02
  text "Supervisor:  Michael M.C. Merlin" at 60.6,93.769 h2.1
  text "Main Contributor:  Chuantong Hao" at 60.6,91.771 h2.1
  text "Top1" at 95.507,91.042 h1.02
  text "Bottom2" at 0.584,90.603 h1.02
  text "Other Contributors:" at 60.6,89.9 h1.4
  text "Michal Szymanowski" at 70.9,89.9 h1.4
  text "Keshuo Lin" at 81.6,89.9 h1.4
  text "Micro MMC v2.0 (2021)" at 19.8,88.7 h2.7
  text "Maciej Muszynski" at 70.9,88.6 h1.4
  text "Ruiyin Wu" at 81.6,88.6 h1.4
  text "A" at 63.194,83.5 h2
  text "A" at 37.365,83.373 h2
  text "Vstack+" at 89.499,82.303 h1.02
  text "Vstack-" at 4.403,82.203 h1.02
  text "Top2" at 13.738,78.042 h1.02
  text "Bottom1" at 80.153,77.903 h1.02
  text "U4" at 88.128,73.727 h0.76
  text "D1" at 14.989,73.332 h0.76
  text "R3" at 17.127,73.327 h0.76
  text "C5" at 6.627,72.832 h0.76
  text "C4" at 77.39,72.824 h0.76
  text "D3" at 24.427,72.542 h0.76
  text "U1" at 29.127,72.327 h0.76
  text "C10" at 16.627,72.252 h0.76
  text "C1" at 65.927,70.927 h0.76
  text "VR2" at 83.084,70.865 h0.76
  text "C12" at 92.388,70.499 h0.76
  text "C3" at 15.157,70.127 h0.76
  text "C11" at 6.027,69.599 h0.76
  text "Vcap" at 1.327,69.581 h0.76
  text "GND_SM" at 95.127,69.554 h0.76
  text "Fv" at 38.366,68.223 h1.27
  text "R1" at 22.142,67.557 h0.76
  text "C7" at 63.527,67.434 h0.76
  text "C6" at 81.827,67.32 h0.76
  text "C8" at 92.388,67.234 h0.76
  text "C9" at 76.55,67.134 h0.76
  text "R4" at 17.104,66.929 h0.76
  text "EN" at 60.4,66.926 h1.27
  text "PWM1" at 38.366,66.89 h1.27
  text "R2" at 14.901,66.802 h0.76
  text "U3" at 19.556,66.802 h0.76
  text "C2" at 79.357,66.62 h0.76
  text "U2" at 10.697,66.227 h0.76
  text "D2" at 88.938,66.217 h0.76
  text "PWM2" at 58.966,65.654 h1.27
  text "OUT2" at 96.327,65.627 h0.76
  text "OUT1" at 1.577,65.611 h0.76
  text "PWM2" at 38.366,65.558 h1.27
  text "D2" at 10.147,65.027 h0.76
  text "U2" at 88.127,64.954 h0.76
  text "U3" at 79.484,64.594 h0.76
  text "R2" at 84.253,64.532 h0.76
  text "C2" at 19.669,64.527 h0.76
  text "R4" at 81.927,64.444 h0.76
  text "PWM1" at 58.966,64.384 h1.27
  text "EN" at 38.366,64.236 h1.27
  text "C9" at 22.527,64.127 h0.76
  text "C8" at 6.627,64.027 h0.76
  text "C6" at 17.104,63.868 h0.76
  text "Fv" at 60.879,63.123 h1.27
  text "C7" at 36.927,62.127 h0.76
  text "OUT2" at 1.131,61.827 h0.76
  text "OUT1" at 96.327,61.827 h0.76
  text "C11" at 92.515,61.692 h0.76
  text "I-" at 46,61.4 h1.27
  text "I+" at 50,61.4 h1.27
  text "Relay" at 47.2,61.372 h1.27
  text "C3" at 83.83,61.032 h0.76
  text "C12" at 5.727,60.827 h0.76
  text "R1" at 77.117,60.514 h0.76
  text "C4" at 24.877,60.342 h0.76
  text "C1" at 33.272,60.247 h0.76
  text "VR2" at 15.14,60.192 h0.76
  text "GND" at 55.5,59.426 h1.27
  text "U1" at 70.153,59.027 h0.76
  text "C10" at 81.75,58.929 h0.76
  text "D3" at 74.565,58.739 h0.76
  text "C5" at 92.388,58.429 h0.76
  text "GND_SM" at 0.427,58.154 h0.76
  text "Vcap" at 96.127,58.081 h0.76
  text "R3" at 81.821,57.974 h0.76
  text "D1" at 84.225,57.974 h0.76
  text "U4" at 10.827,57.527 h0.76
  text "U4" at 88.128,57.171 h0.76
  text "D1" at 15.013,56.632 h0.76
  text "D1" at 15.013,56.632 h0.76
  text "R3" at 17.151,56.627 h0.76
  text "C4" at 77.39,56.268 h0.76
  text "C5" at 6.651,56.132 h0.76
  text "C5" at 6.651,56.132 h0.76
  text "D3" at 24.451,55.842 h0.76
  text "D3" at 24.451,55.842 h0.76
  text "U1" at 29.151,55.627 h0.76
  text "U1" at 29.151,55.627 h0.76
  text "C10" at 16.651,55.552 h0.76
  text "C1" at 65.927,54.371 h0.76
  text "VR2" at 83.084,54.309 h0.76
  text "3.3V" at 50.5,54.221 h1.27
  text "C12" at 92.388,53.943 h0.76
  text "C3" at 15.181,53.427 h0.76
  text "Vcap" at 1.427,52.981 h0.76
  text "GND_SM" at 95.154,52.925 h0.76
  text "C11" at 6.051,52.899 h0.76
  text "Fv" at 38.304,51.523 h1.27
  text "R1" at 22.165,50.857 h0.76
  text "R1" at 22.165,50.857 h0.76
  text "C6" at 81.827,50.764 h0.76
  text "C8" at 92.388,50.678 h0.76
  text "C9" at 76.55,50.578 h0.76
  text "EN" at 60.486,50.426 h1.27
  text "R4" at 17.128,50.229 h0.76
  text "PWM1" at 38.304,50.224 h1.27
  text "R2" at 14.925,50.102 h0.76
  text "R2" at 14.925,50.102 h0.76
  text "U3" at 19.58,50.102 h0.76
  text "C2" at 79.357,50.064 h0.76
  text "D2" at 88.938,49.661 h0.76
  text "U2" at 10.721,49.527 h0.76
  text "PWM2" at 58.966,49.154 h1.27
  text "OUT2" at 96.327,49.071 h0.76
  text "OUT1" at 1.554,49.038 h0.76
  text "PWM2" at 38.304,48.924 h1.27
  text "U2" at 88.127,48.398 h0.76
  text "D2" at 10.171,48.327 h0.76
  text "U3" at 79.484,48.038 h0.76
  text "R2" at 84.253,47.976 h0.76
  text "PWM1" at 58.966,47.884 h1.27
  text "R4" at 81.927,47.888 h0.76
  text "C2" at 19.693,47.827 h0.76
  text "EN" at 38.304,47.636 h1.27
  text "C9" at 22.551,47.427 h0.76
  text "C9" at 22.551,47.427 h0.76
  text "C8" at 6.651,47.327 h0.76
  text "C6" at 17.226,47.227 h0.76
  text "Fv" at 60.879,46.623 h1.27
  text "C7" at 36.951,45.627 h0.76
  text "OUT2" at 1.354,45.254 h0.76
  text "OUT1" at 96.327,45.271 h0.76
  text "C11" at 92.515,45.136 h0.76
  text "C3" at 83.83,44.476 h0.76
  text "C12" at 5.751,44.127 h0.76
  text "R1" at 77.117,43.958 h0.76
  text "C4" at 24.9,43.642 h0.76
  text "C1" at 33.254,43.547 h0.76
  text "VR2" at 15.163,43.492 h0.76
  text "U1" at 70.153,42.471 h0.76
  text "C10" at 81.75,42.373 h0.76
  text "D3" at 74.565,42.183 h0.76
  text "C5" at 92.388,41.873 h0.76
  text "D2" at 14.925,41.581 h0.76
  text "Vcap" at 96.127,41.525 h0.76
  text "GND_SM" at 0.427,41.454 h0.76
  text "R3" at 81.821,41.418 h0.76
  text "D1" at 84.225,41.418 h0.76
  text "U4" at 10.727,40.827 h0.76
  text "U4" at 88.037,40.371 h0.76
  text "D1" at 15.013,39.937 h0.76
  text "D1" at 15.052,39.937 h0.76
  text "R3" at 17.151,39.932 h0.76
  text "C4" at 77.299,39.468 h0.76
  text "C5" at 6.651,39.356 h0.76
  text "D3" at 24.451,39.242 h0.76
  text "C10" at 16.651,38.857 h0.76
  text "U1" at 29.135,38.832 h0.76
  text "C1" at 65.836,37.571 h0.76
  text "VR2" at 82.993,37.509 h0.76
  text "C12" at 92.297,37.143 h0.76
  text "C3" at 15.181,36.732 h0.76
  text "Vcap" at 1.227,36.281 h0.76
  text "C11" at 6.051,36.204 h0.76
  text "GND_SM" at 95.063,36.125 h0.76
  text "Fv" at 38.304,34.723 h1.27
  text "R1" at 22.165,34.257 h0.76
  text "C6" at 81.736,33.964 h0.76
  text "C8" at 92.297,33.878 h0.76
  text "C9" at 76.459,33.778 h0.76
  text "EN" at 60.286,33.626 h1.27
  text "R4" at 17.128,33.534 h0.76
  text "PWM1" at 38.304,33.424 h1.27
  text "R2" at 14.925,33.407 h0.76
  text "U3" at 19.58,33.407 h0.76
  text "C2" at 79.267,33.264 h0.76
  text "D2" at 88.847,32.861 h0.76
  text "U2" at 10.721,32.832 h0.76
  text "OUT1" at 1.354,32.427 h0.76
  text "PWM2" at 58.766,32.354 h1.27
  text "OUT2" at 96.236,32.271 h0.76
  text "PWM2" at 38.304,32.124 h1.27
  text "D2" at 10.171,31.632 h0.76
  text "U2" at 88.036,31.598 h0.76
  text "U3" at 79.394,31.238 h0.76
  text "R2" at 84.162,31.176 h0.76
  text "C2" at 19.693,31.132 h0.76
  text "PWM1" at 58.766,31.084 h1.27
  text "R4" at 81.836,31.088 h0.76
  text "EN" at 38.304,30.836 h1.27
  text "C9" at 22.515,30.787 h0.76
  text "C8" at 6.651,30.632 h0.76
  text "C6" at 17.226,30.627 h0.76
  text "Fv" at 60.679,29.823 h1.27
  text "JLCJLCJLCJLC" at 44.18,29.804 h1
  text "C7" at 36.927,28.912 h0.76
  text "OUT2" at 1.481,28.627 h0.76
  text "OUT1" at 96.236,28.471 h0.76
  text "C11" at 92.424,28.336 h0.76
  text "C3" at 83.739,27.676 h0.76
  text "C12" at 5.751,27.432 h0.76
  text "R1" at 77.027,27.157 h0.76
  text "C4" at 24.9,26.947 h0.76
  text "C1" at 33.254,26.852 h0.76
  text "VR2" at 15.163,26.797 h0.76
  text "U1" at 70.062,25.671 h0.76
  text "C10" at 81.659,25.573 h0.76
  text "D3" at 74.474,25.383 h0.76
  text "C5" at 92.297,25.073 h0.76
  text "GND_SM" at 0.727,24.786 h0.76
  text "Vcap" at 96.036,24.725 h0.76
  text "R3" at 81.73,24.617 h0.76
  text "D1" at 84.134,24.617 h0.76
  text "U4" at 10.827,24.127 h0.76
  text "U4" at 88.239,23.497 h0.76
  text "D1" at 15.013,23.252 h0.76
  text "R3" at 17.151,23.247 h0.76
  text "D1" at 15.065,23.205 h0.76
  text "C5" at 6.651,22.752 h0.76
  text "C4" at 77.5,22.594 h0.76
  text "D3" at 24.451,22.462 h0.76
  text "D3" at 24.503,22.415 h0.76
  text "U1" at 29.203,22.2 h0.76
  text "C10" at 16.651,22.172 h0.76
  text "C1" at 66.037,20.697 h0.76
  text "VR2" at 83.194,20.635 h0.76
  text "C12" at 92.498,20.269 h0.76
  text "C3" at 15.181,20.047 h0.76
  text "C11" at 6.051,19.519 h0.76
  text "Vcap" at 1.227,19.481 h0.76
  text "GND_SM" at 95.264,19.251 h0.76
  text "Fv" at 38.204,18.123 h1.27
  text "R1" at 22.165,17.477 h0.76
  text "C6" at 81.937,17.09 h0.76
  text "C8" at 92.498,17.004 h0.76
  text "C9" at 76.66,16.904 h0.76
  text "R4" at 17.128,16.849 h0.76
  text "PWM1" at 38.204,16.824 h1.27
  text "U3" at 19.58,16.722 h0.76
  text "EN" at 60.486,16.726 h1.27
  text "R2" at 14.978,16.675 h0.76
  text "C2" at 79.468,16.39 h0.76
  text "U2" at 10.721,16.147 h0.76
  text "D2" at 89.048,15.987 h0.76
  text "OUT1" at 1.527,15.627 h0.76
  text "PWM2" at 38.204,15.524 h1.27
  text "PWM2" at 58.966,15.454 h1.27
  text "OUT2" at 96.437,15.397 h0.76
  text "D2" at 10.171,14.947 h0.76
  text "U2" at 88.237,14.724 h0.76
  text "C2" at 19.693,14.447 h0.76
  text "U3" at 79.595,14.364 h0.76
  text "R2" at 84.364,14.302 h0.76
  text "EN" at 38.204,14.236 h1.27
  text "R4" at 82.037,14.214 h0.76
  text "PWM1" at 58.966,14.184 h1.27
  text "C9" at 22.551,14.047 h0.76
  text "C8" at 6.651,13.947 h0.76
  text "C6" at 17.278,13.8 h0.76
  text "Fv" at 60.879,12.923 h1.27
  text "C7" at 36.927,12.227 h0.76
  text "OUT2" at 1.527,11.927 h0.76
  text "OUT1" at 96.437,11.597 h0.76
  text "C11" at 92.625,11.462 h0.76
  text "C3" at 83.941,10.802 h0.76
  text "C12" at 5.751,10.747 h0.76
  text "R1" at 77.228,10.284 h0.76
  text "C4" at 24.9,10.262 h0.76
  text "C1" at 33.5,10.167 h0.76
  text "VR2" at 15.163,10.112 h0.76
  text "U1" at 70.263,8.797 h0.76
  text "C10" at 81.86,8.699 h0.76
  text "D3" at 74.675,8.509 h0.76
  text "C5" at 92.498,8.199 h0.76
  text "GND_SM" at 0.627,8.101 h0.76
  text "JTAG" at 59.1,7.979 h1.27
  text "Vcap" at 96.237,7.851 h0.76
  text "R3" at 81.932,7.744 h0.76
  text "D1" at 84.335,7.744 h0.76
  text "SPI" at 38.2,7.719 h1.27
  text "5V" at 34.4,7.621 h1.27
  text "U4" at 10.827,7.427 h0.76
  text "3.3V" at 54.5,1.221 h1.27
Bottom Overlay:
  lines w0.5: 1,76 99,76
  text "VR1" at 78.473,70.527 h0.76
  text "Vcap" at 4.173,69.581 h0.76
  text "GND_SM" at 99.473,69.554 h0.76
  text "Fv" at 39.554,68.223 h1.27
  text "EN" at 61.966,66.926 h1.27
  text "PWM1" at 41.466,66.89 h1.27
  text "P1" at 76.873,66.127 h0.76
  text "PWM2" at 61.966,65.654 h1.27
  text "OUT2" at 99.073,65.627 h0.76
  text "OUT1" at 3.973,65.611 h0.76
  text "PWM2" at 41.466,65.558 h1.27
  text "P1" at 24.389,65.127 h0.76
  text "PWM1" at 61.966,64.384 h1.27
  text "EN" at 39.947,64.236 h1.27
  text "Fv" at 61.966,63.123 h1.27
  text "OUT2" at 3.873,61.827 h0.76
  text "OUT1" at 98.873,61.827 h0.76
  text "VR1" at 23.358,60.469 h0.76
  text "Csm" at 19.593,58.609 h0.76
  text "Csm" at 94.782,58.54 h0.76
  text "GND_SM" at 4.773,58.154 h0.76
  text "Vcap" at 98.873,58.081 h0.76
  text "VR1" at 78.473,53.971 h0.76
  text "Vcap" at 4.173,52.981 h0.76
  text "GND_SM" at 99.473,52.925 h0.76
  text "Fv" at 39.55,51.523 h1.27
  text "EN" at 61.966,50.426 h1.27
  text "PWM1" at 41.366,50.224 h1.27
  text "P1" at 76.873,49.571 h0.76
  text "PWM2" at 61.966,49.154 h1.27
  text "OUT2" at 99.073,49.071 h0.76
  text "OUT1" at 3.97,49.038 h0.76
  text "PWM2" at 41.366,48.924 h1.27
  text "P1" at 24.396,48.427 h0.76
  text "P1" at 24.413,48.427 h0.76
  text "PWM1" at 61.966,47.884 h1.27
  text "EN" at 39.943,47.636 h1.27
  text "Fv" at 61.966,46.623 h1.27
  text "OUT2" at 4.097,45.254 h0.76
  text "OUT1" at 98.873,45.271 h0.76
  text "VR1" at 23.404,43.845 h0.76
  text "Csm" at 19.717,42.139 h0.76
  text "Csm" at 94.782,41.984 h0.76
  text "Vcap" at 98.873,41.525 h0.76
  text "GND_SM" at 4.673,41.454 h0.76
  text "VR1" at 78.382,37.171 h0.76
  text "Vcap" at 4.073,36.281 h0.76
  text "GND_SM" at 99.373,36.125 h0.76
  text "Fv" at 39.55,34.723 h1.27
  text "EN" at 61.766,33.626 h1.27
  text "PWM1" at 41.366,33.424 h1.27
  text "P1" at 76.782,32.771 h0.76
  text "OUT1" at 3.847,32.427 h0.76
  text "PWM2" at 61.766,32.354 h1.27
  text "OUT2" at 98.982,32.271 h0.76
  text "PWM2" at 41.366,32.124 h1.27
  text "P1" at 24.382,31.732 h0.76
  text "P1" at 24.413,31.732 h0.76
  text "PWM1" at 61.766,31.084 h1.27
  text "EN" at 39.943,30.836 h1.27
  text "Fv" at 61.766,29.823 h1.27
  text "OUT2" at 4.173,28.627 h0.76
  text "OUT1" at 98.782,28.471 h0.76
  text "VR1" at 23.382,27.074 h0.76
  text "Csm" at 19.617,25.214 h0.76
  text "Csm" at 94.691,25.184 h0.76
  text "GND_SM" at 4.997,24.786 h0.76
  text "Vcap" at 98.782,24.725 h0.76
  text "VR1" at 78.583,20.297 h0.76
  text "Vcap" at 4.073,19.473 h0.76
  text "GND_SM" at 99.56,19.267 h0.76
  text "Fv" at 39.55,18.123 h1.27
  text "PWM1" at 41.366,16.824 h1.27
  text "EN" at 61.987,16.703 h1.27
  text "P1" at 76.983,15.897 h0.76
  text "OUT1" at 3.847,15.627 h0.76
  text "PWM2" at 41.366,15.524 h1.27
  text "PWM2" at 61.987,15.431 h1.27
  text "OUT2" at 99.183,15.397 h0.76
  text "P1" at 24.401,15.047 h0.76
  text "P1" at 24.413,15.047 h0.76
  text "EN" at 39.943,14.236 h1.27
  text "PWM1" at 61.987,14.161 h1.27
  text "Fv" at 61.987,12.9 h1.27
  text "OUT2" at 4.273,11.894 h0.76
  text "OUT1" at 98.983,11.597 h0.76
  text "VR1" at 23.382,10.609 h0.76
  text "Csm" at 19.617,8.529 h0.76
  text "Csm" at 94.892,8.31 h0.76
  text "GND_SM" at 4.997,8.101 h0.76
  text "Vcap" at 98.983,7.851 h0.76
Mechanical 1:
  lines w0.254: 100,2.3 99.986,97.46 ccw(c97.446,97.46) 97.446,100 2.3,100 ccw(c2.414,97.574) -0.012,97.46 0,2.3 ccw(c2.3,2.3) 2.3,0 97.7,0 ccw(c97.582,2.418) 100,2.537 ; 28.6,11.2 30.5,11.2 30.5,21.8 28.6,21.8 28.6,11.2 ; 28.6,27.9 28.6,38.5 30.5,38.5 30.5,27.9 28.6,27.9 ; 28.6,44.6 30.5,44.6 30.5,55.2 28.6,55.2 28.6,44.6 ; 28.6,61.3 30.5,61.3 30.5,71.9 28.6,71.9 28.6,61.3 ; 34.8,75.3 34.8,76.9 42.3,76.9 42.3,75.3 34.8,75.3 ; 43.5,70.9 56.6,70.9 56.6,72.5 43.5,72.5 43.5,70.9 ; 57.1,75.3 64.6,75.3 64.6,76.9 57.1,76.9 57.1,75.3 ; 69.6,26.8 69.6,37.4 71.5,37.4 71.5,26.8 69.6,26.8 ; 69.7,43.6 69.7,54.2 71.6,54.2 71.6,43.6 69.7,43.6 ; 69.7,60.2 69.7,70.7 71.6,70.7 71.6,60.2 69.7,60.2 ; 69.8,9.9 71.7,9.9 71.7,20.5 69.8,20.5 69.8,9.9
